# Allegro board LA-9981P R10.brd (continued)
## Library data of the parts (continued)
YG1 YL2 = Y_FSX3M-25PM20FDO_4P
YV1 = Y_7V27000011_4P

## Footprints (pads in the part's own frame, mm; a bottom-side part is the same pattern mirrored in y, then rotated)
2N7002DW-T-R7_SOT363-6
  oval 0.381x1.397 smd: 1(0,0) 2(0.65,0) 3(1.3,0) 4(1.3,1.725) 5(0.65,1.725) 6(0,1.725)
2N7002K_SOT23-3
  oval 1.016x1.524 smd: 1(0,0) 2(0.965,2.083) 3(-0.965,2.083)
2N7002KW_SOT323-3
  oval 0.813x0.914 smd: 1(0,0) 2(0.65,1.6) 3(-0.65,1.6)
2N7002W-T-R7_SOT323-3
  oval 0.813x0.914 smd: 1(0,0) 2(0.65,1.6) 3(-0.65,1.6)
74AUP1G07GW_TSSOP5
  oval 0.381x1.346 smd: 1(0,0) 2(0.65,0) 3(1.3,0) 4(1.3,1.79) 5(0,1.79)
74CBTLV3126BQ_DHVQFN14_2P5X3
  oval 1.041x0.254 smd: 1(0,0) 7(2.95,0) 8(2.95,0.5) 14(0,0.5)
  oval 0.254x1.041 smd: 2(0.475,-0.975) 3(0.975,-0.975) 4(1.475,-0.975) 5(1.975,-0.975) 6(2.475,-0.975) 9(2.475,1.475) 10(1.975,1.475) 11(1.475,1.475) 12(0.975,1.475) 13(0.475,1.475)
  rect 1.499x0.991 smd: 15(1.475,0.25)
2160809000A11SEYMOU_FCBGA_962P
  round 0.508 smd: A3(0.8,0) A37(26.8,0) A39(27.6,0) AA9(4.8,-15) AA10(5.6,-15) AA11(6.4,-14.4) AA12(7.4,-14.4) AA13(8.4,-14.4) AA15(9.4,-14.4) AA16(10.4,-14.4) AA17(11.4,-14.4) AA18(12.4,-14.4) AA20(13.4,-14.4) AA21(14.4,-14.4) AA22(15.4,-14.4) AA23(16.4,-14.4) AA24(17.4,-14.4) AA26(18.4,-14.4) AA27(19.4,-14.4) AA28(20.4,-14.4) AA29(21.2,-15) AA30(22,-15) AA31(22.8,-15) AB11(6.4,-15.4) AB12(7.4,-15.4) AB13(8.4,-15.4) AB15(9.4,-15.4) AB16(10.4,-15.4) AB17(11.4,-15.4) AB18(12.4,-15.4) AB20(13.4,-15.4) AB21(14.4,-15.4) AB22(15.4,-15.4) AB23(16.4,-15.4) AB24(17.4,-15.4) AB26(18.4,-15.4) AB27(19.4,-15.4) AB28(20.4,-15.4) AC10(5.6,-16.2) AC11(6.4,-16.4) AC12(7.4,-16.4) AC13(8.4,-16.4) AC15(9.4,-16.4) AC16(10.4,-16.4) AC17(11.4,-16.4) AC18(12.4,-16.4) AC20(13.4,-16.4) AC21(14.4,-16.4) AC22(15.4,-16.4) AC23(16.4,-16.4) AC24(17.4,-16.4) AC26(18.4,-16.4) AC27(19.4,-16.4) AC28(20.4,-16.4) AC29(21.2,-16.2) AC30(22,-16.2) AD11(6.4,-17.4) AD12(7.4,-17.4) AD13(8.4,-17.4) AD15(9.4,-17.4) AD16(10.4,-17.4) AD17(11.4,-17.4) AD18(12.4,-17.4) AD20(13.4,-17.4) AD21(14.4,-17.4) AD22(15.4,-17.4) AD23(16.4,-17.4) AD24(17.4,-17.4) AD26(18.4,-17.4) AD27(19.4,-17.4) AD28(20.4,-17.4) AD29(21.2,-17.4) AF12(7.4,-18.4) AF13(8.4,-18.4) AF15(9.4,-18.4) AF16(10.4,-18.4) AF17(11.4,-18.4) AF18(12.4,-18.4) AF20(13.4,-18.4) AF21(14.4,-18.4) AF22(15.4,-18.4) AF23(16.4,-18.4) AF24(17.4,-18.4) AF26(18.4,-18.4) AF27(19.4,-18.4) AF28(20.4,-18.4) AG13(8.4,-19.4) AG15(9.4,-19.4) AG16(10.4,-19.4) AG17(11.4,-19.4) AG18(12.4,-19.4) AG20(13.4,-19.4) AG21(14.4,-19.4) AG22(15.4,-19.4) AG23(16.4,-19.4) AG24(17.4,-19.4) AG26(18.4,-19.4) AG27(19.4,-19.4) AH15(9.4,-20.4) AH16(10.4,-20.4) AH17(11.4,-20.4) AH18(12.4,-20.4) AH20(13.4,-20.4) AH21(14.4,-20.4) AH22(15.4,-20.4) AH23(16.4,-20.4) AH24(17.4,-20.4) AH26(18.4,-20.4) AJ16(10.2,-21.2) AJ17(11.4,-21.2) AJ19(12.6,-21.2) AJ20(13.8,-21.2) AJ21(15,-21.2) AJ23(16.2,-21.2) AJ24(17.4,-21.2) AK17(11.4,-22) AK19(12.6,-22) AK20(13.8,-22) AK21(15,-22) AK23(16.2,-22) AL19(12.6,-22.8) AL20(13.8,-22.8) AL21(15,-22.8) AM20(13.8,-23.6) AU1(0,-26.8) AU3(0.8,-26.8) AU37(26.8,-26.8) AU39(27.6,-26.8) AW1(0,-27.6) AW3(0.8,-27.6) AW37(26.8,-27.6) AW39(27.6,-27.6) C1(0,-0.8) C3(0.8,-0.8) C37(26.8,-0.8) C39(27.6,-0.8) H20(13.8,-4) J19(12.6,-4.8) J20(13.8,-4.8) J21(15,-4.8) K17(11.4,-5.6) K19(12.6,-5.6) K20(13.8,-5.6) K21(15,-5.6) K23(16.2,-5.6) L16(10.4,-6.4) L17(11.4,-6.4) L18(12.4,-6.4) L20(13.4,-6.4) L21(14.4,-6.4) L22(15.4,-6.4) L23(16.4,-6.4) L24(17.4,-6.4) M15(9.4,-7.4) M16(10.4,-7.4) M17(11.4,-7.4) M18(12.4,-7.4) M20(13.4,-7.4) M21(14.4,-7.4) M22(15.4,-7.4) M23(16.4,-7.4) M24(17.4,-7.4) M26(18.4,-7.4) N13(8.4,-8.4) N15(9.4,-8.4) N16(10.4,-8.4) N17(11.4,-8.4) N18(12.4,-8.4) N20(13.4,-8.4) N21(14.4,-8.4) N22(15.4,-8.4) N23(16.4,-8.4) N24(17.4,-8.4) N26(18.4,-8.4) N27(19.4,-8.4) R12(7.4,-9.4) R13(8.4,-9.4) R15(9.4,-9.4) R16(10.4,-9.4) R17(11.4,-9.4) R18(12.4,-9.4) R20(13.4,-9.4) R21(14.4,-9.4) R22(15.4,-9.4) R23(16.4,-9.4) R24(17.4,-9.4) R26(18.4,-9.4) R27(19.4,-9.4) R28(20.4,-9.4) T11(6.4,-10.4) T12(7.4,-10.4) T13(8.4,-10.4) T15(9.4,-10.4) T16(10.4,-10.4) T17(11.4,-10.4) T18(12.4,-10.4) T20(13.4,-10.4) T21(14.4,-10.4) T22(15.4,-10.4) T23(16.4,-10.4) T24(17.4,-10.4) T26(18.4,-10.4) T27(19.4,-10.4) T28(20.4,-10.4) T29(21.2,-10.2) U10(5.6,-11.4) U11(6.4,-11.4) U12(7.4,-11.4) U13(8.4,-11.4) U15(9.4,-11.4) U16(10.4,-11.4) U17(11.4,-11.4) U18(12.4,-11.4) U20(13.4,-11.4) U21(14.4,-11.4) U22(15.4,-11.4) U23(16.4,-11.4) U24(17.4,-11.4) U26(18.4,-11.4) U27(19.4,-11.4) U28(20.4,-11.4) U29(21.2,-11.4) U30(22,-11.4) V11(6.4,-12.4) V12(7.4,-12.4) V13(8.4,-12.4) V15(9.4,-12.4) V16(10.4,-12.4) V17(11.4,-12.4) V18(12.4,-12.4) V20(13.4,-12.4) V21(14.4,-12.4) V22(15.4,-12.4) V23(16.4,-12.4) V24(17.4,-12.4) V26(18.4,-12.4) V27(19.4,-12.4) V28(20.4,-12.4) W9(4.8,-12.6) W10(5.6,-12.6) W29(21.2,-12.6) W30(22,-12.6) W31(22.8,-12.6) Y8(4,-13.8) Y9(4.8,-13.8) Y10(5.6,-13.8) Y11(6.4,-13.4) Y12(7.4,-13.4) Y13(8.4,-13.4) Y15(9.4,-13.4) Y16(10.4,-13.4) Y17(11.4,-13.4) Y18(12.4,-13.4) Y20(13.4,-13.4) Y21(14.4,-13.4) Y22(15.4,-13.4) Y23(16.4,-13.4) Y24(17.4,-13.4) Y26(18.4,-13.4) Y27(19.4,-13.4) Y28(20.4,-13.4) Y29(21.2,-13.8) Y30(22,-13.8) Y31(22.8,-13.8) Y32(23.6,-13.8)
  round 0.305 smd: A5(1.7,0) A6(2.6,0) A8(4.2,0) A10(5.8,0) A12(7.4,0) A14(9,0) A16(10.6,0) A18(12.2,0) A20(13.8,0) A22(15.4,0) A24(17,0) A26(18.6,0) A28(20.2,0) A30(21.8,0) A32(23.4,0) A34(25,0) A35(25.9,0) AA2(0.4,-14.6) AA4(1.2,-14.6) AA6(2.4,-14.8) AA34(25.2,-14.8) AA36(26.4,-14.6) AA38(27.2,-14.6) AB1(0,-15.4) AB3(0.8,-15.4) AB5(1.6,-15.4) AB6(2.4,-15.6) AB34(25.2,-15.6) AB35(26,-15.4) AB37(26.8,-15.4) AB39(27.6,-15.4) AC2(0.4,-16.2) AC4(1.2,-16.2) AC6(2.4,-16.4) AC34(25.2,-16.4) AC36(26.4,-16.2) AC38(27.2,-16.2) AD1(0,-17) AD3(0.8,-17) AD5(1.6,-17) AD6(2.4,-17.2) AD34(25.2,-17.2) AD35(26,-17) AD37(26.8,-17) AD39(27.6,-17) AE2(0.4,-17.8) AE4(1.2,-17.8) AE6(2.4,-18) AE34(25.2,-18) AE36(26.4,-17.8) AE38(27.2,-17.8) AF1(0,-18.6) AF3(0.8,-18.6) AF5(1.6,-18.6) AF6(2.4,-18.8) AF34(25.2,-18.8) AF35(26,-18.6) AF37(26.8,-18.6) AF39(27.6,-18.6) AG2(0.4,-19.4) AG4(1.2,-19.4) AG6(2.4,-19.6) AG34(25.2,-19.6) AG36(26.4,-19.4) AG38(27.2,-19.4) AH1(0,-20.2) AH3(0.8,-20.2) AH5(1.6,-20.2) AH6(2.4,-20.4) AH34(25.2,-20.4) AH35(26,-20.2) AH37(26.8,-20.2) AH39(27.6,-20.2) AJ2(0.4,-21) AJ4(1.2,-21) AJ6(2.4,-21.2) AJ34(25.2,-21.2) AJ36(26.4,-21) AJ38(27.2,-21) AK1(0,-21.8) AK3(0.8,-21.8) AK5(1.6,-21.8) AK6(2.4,-22) AK34(25.2,-22) AK35(26,-21.8) AK37(26.8,-21.8) AK39(27.6,-21.8) AL2(0.4,-22.6) AL4(1.2,-22.6) AL6(2.4,-22.8) AL34(25.2,-22.8) AL36(26.4,-22.6) AL38(27.2,-22.6) AM1(0,-23.4) AM3(0.8,-23.4) AM5(1.6,-23.4) AM6(2.4,-23.6) AM34(25.2,-23.6) AM35(26,-23.4) AM37(26.8,-23.4) AM39(27.6,-23.4) AN2(0.4,-24.2) AN4(1.2,-24.2) AN6(2.4,-24.4) AN34(25.2,-24.4) AN36(26.4,-24.2) AN38(27.2,-24.2) AP1(0,-25) AP3(0.8,-25) AP5(1.6,-25) AP6(2.4,-25.2) AP7(3.2,-25.2) AP8(4,-25.2) AP9(4.8,-25.2) AP10(5.6,-25.2) AP11(6.4,-25.2) AP12(7.2,-25.2) AP13(8,-25.2) AP14(8.8,-25.2) AP15(9.6,-25.2) AP16(10.4,-25.2) AP17(11.2,-25.2) AP18(12,-25.2) AP19(12.8,-25.2) AP20(13.8,-25.2) AP21(14.8,-25.2) AP22(15.6,-25.2) AP23(16.4,-25.2) AP24(17.2,-25.2) AP25(18,-25.2) AP26(18.8,-25.2) AP27(19.6,-25.2) AP28(20.4,-25.2) AP29(21.2,-25.2) AP30(22,-25.2) AP31(22.8,-25.2) AP32(23.6,-25.2) AP33(24.4,-25.2) AP34(25.2,-25.2) AP35(26,-25) AP37(26.8,-25) AP39(27.6,-25) AR1(0,-25.9) AR3(0.8,-25.9) AR5(1.7,-25.9) AR6(2.6,-26) AR8(4.2,-26) AR10(5.8,-26) AR12(7.4,-26) AR14(9,-26) AR16(10.6,-26) AR18(12.2,-26) AR20(13.8,-26) AR22(15.4,-26) AR24(17,-26) AR26(18.6,-26) AR28(20.2,-26) AR30(21.8,-26) AR32(23.4,-26) AR34(25,-26) AR35(25.9,-25.9) AR37(26.8,-25.9) AR39(27.6,-25.9) AT7(3.4,-26.4) AT9(5,-26.4) AT11(6.6,-26.4) AT13(8.2,-26.4) AT15(9.8,-26.4) AT17(11.4,-26.4) AT19(13,-26.4) AT21(14.6,-26.4) AT23(16.2,-26.4) AT25(17.8,-26.4) AT27(19.4,-26.4) AT29(21,-26.4) AT31(22.6,-26.4) AT33(24.2,-26.4) AU5(1.7,-26.8) AU6(2.6,-26.8) AU8(4.2,-26.8) AU10(5.8,-26.8) AU12(7.4,-26.8) AU14(9,-26.8) AU16(10.6,-26.8) AU18(12.2,-26.8) AU20(13.8,-26.8) AU22(15.4,-26.8) AU24(17,-26.8) AU26(18.6,-26.8) AU28(20.2,-26.8) AU30(21.8,-26.8) AU32(23.4,-26.8) AU34(25,-26.8) AU35(25.9,-26.8) AV7(3.4,-27.2) AV9(5,-27.2) AV11(6.6,-27.2) AV13(8.2,-27.2) AV15(9.8,-27.2) AV17(11.4,-27.2) AV19(13,-27.2) AV21(14.6,-27.2) AV23(16.2,-27.2) AV25(17.8,-27.2) AV27(19.4,-27.2) AV29(21,-27.2) AV31(22.6,-27.2) AV33(24.2,-27.2) AW5(1.7,-27.6) AW6(2.6,-27.6) AW8(4.2,-27.6) AW10(5.8,-27.6) AW12(7.4,-27.6) AW14(9,-27.6) AW16(10.6,-27.6) AW18(12.2,-27.6) AW20(13.8,-27.6) AW22(15.4,-27.6) AW24(17,-27.6) AW26(18.6,-27.6) AW28(20.2,-27.6) AW30(21.8,-27.6) AW32(23.4,-27.6) AW34(25,-27.6) AW35(25.9,-27.6) B7(3.4,-0.4) B9(5,-0.4) B11(6.6,-0.4) B13(8.2,-0.4) B15(9.8,-0.4) B17(11.4,-0.4) B19(13,-0.4) B21(14.6,-0.4) B23(16.2,-0.4) B25(17.8,-0.4) B27(19.4,-0.4) B29(21,-0.4) B31(22.6,-0.4) B33(24.2,-0.4) C5(1.7,-0.8) C6(2.6,-0.8) C8(4.2,-0.8) C10(5.8,-0.8) C12(7.4,-0.8) C14(9,-0.8) C16(10.6,-0.8) C18(12.2,-0.8) C20(13.8,-0.8) C22(15.4,-0.8) C24(17,-0.8) C26(18.6,-0.8) C28(20.2,-0.8) C30(21.8,-0.8) C32(23.4,-0.8) C34(25,-0.8) C35(25.9,-0.8) D7(3.4,-1.2) D9(5,-1.2) D11(6.6,-1.2) D13(8.2,-1.2) D15(9.8,-1.2) D17(11.4,-1.2) D19(13,-1.2) D21(14.6,-1.2) D23(16.2,-1.2) D25(17.8,-1.2) D27(19.4,-1.2) D29(21,-1.2) D31(22.6,-1.2) D33(24.2,-1.2) E1(0,-1.7) E3(0.8,-1.7) E5(1.7,-1.7) E6(2.6,-1.6) E8(4.2,-1.6) E10(5.8,-1.6) E12(7.4,-1.6) E14(9,-1.6) E16(10.6,-1.6) E18(12.2,-1.6) E20(13.8,-1.6) E22(15.4,-1.6) E24(17,-1.6) E26(18.6,-1.6) E28(20.2,-1.6) E30(21.8,-1.6) E32(23.4,-1.6) E34(25,-1.6) E35(25.9,-1.7) E37(26.8,-1.7) E39(27.6,-1.7) F1(0,-2.6) F3(0.8,-2.6) F5(1.6,-2.6) F6(2.4,-2.4) F7(3.2,-2.4) F8(4,-2.4) F9(4.8,-2.4) F10(5.6,-2.4) F11(6.4,-2.4) F12(7.2,-2.4) F13(8,-2.4) F14(8.8,-2.4) F15(9.6,-2.4) F16(10.4,-2.4) F17(11.2,-2.4) F18(12,-2.4) F19(12.8,-2.4) F20(13.8,-2.4) F21(14.8,-2.4) F22(15.6,-2.4) F23(16.4,-2.4) F24(17.2,-2.4) F25(18,-2.4) F26(18.8,-2.4) F27(19.6,-2.4) F28(20.4,-2.4) F29(21.2,-2.4) F30(22,-2.4) F31(22.8,-2.4) F32(23.6,-2.4) F33(24.4,-2.4) F34(25.2,-2.4) F35(26,-2.6) F37(26.8,-2.6) F39(27.6,-2.6) G2(0.4,-3.4) G4(1.2,-3.4) G6(2.4,-3.2) G34(25.2,-3.2) G36(26.4,-3.4) G38(27.2,-3.4) H1(0,-4.2) H3(0.8,-4.2) H5(1.6,-4.2) H6(2.4,-4) H34(25.2,-4) H35(26,-4.2) H37(26.8,-4.2) H39(27.6,-4.2) J2(0.4,-5) J4(1.2,-5) J6(2.4,-4.8) J34(25.2,-4.8) J36(26.4,-5) J38(27.2,-5) K1(0,-5.8) K3(0.8,-5.8) K5(1.6,-5.8) K6(2.4,-5.6) K34(25.2,-5.6) K35(26,-5.8) K37(26.8,-5.8) K39(27.6,-5.8) L2(0.4,-6.6) L4(1.2,-6.6) L6(2.4,-6.4) L34(25.2,-6.4) L36(26.4,-6.6) L38(27.2,-6.6) M1(0,-7.4) M3(0.8,-7.4) M5(1.6,-7.4) M6(2.4,-7.2) M34(25.2,-7.2) M35(26,-7.4) M37(26.8,-7.4) M39(27.6,-7.4) N2(0.4,-8.2) N4(1.2,-8.2) N6(2.4,-8) N34(25.2,-8) N36(26.4,-8.2) N38(27.2,-8.2) P1(0,-9) P3(0.8,-9) P5(1.6,-9) P6(2.4,-8.8) P34(25.2,-8.8) P35(26,-9) P37(26.8,-9) P39(27.6,-9) R2(0.4,-9.8) R4(1.2,-9.8) R6(2.4,-9.6) R34(25.2,-9.6) R36(26.4,-9.8) R38(27.2,-9.8) T1(0,-10.6) T3(0.8,-10.6) T5(1.6,-10.6) T6(2.4,-10.4) T34(25.2,-10.4) T35(26,-10.6) T37(26.8,-10.6) T39(27.6,-10.6) U2(0.4,-11.4) U4(1.2,-11.4) U6(2.4,-11.2) U34(25.2,-11.2) U36(26.4,-11.4) U38(27.2,-11.4) V1(0,-12.2) V3(0.8,-12.2) V5(1.6,-12.2) V6(2.4,-12) V34(25.2,-12) V35(26,-12.2) V37(26.8,-12.2) V39(27.6,-12.2) W2(0.4,-13) W4(1.2,-13) W6(2.4,-12.8) W34(25.2,-12.8) W36(26.4,-13) W38(27.2,-13) Y1(0,-13.8) Y3(0.8,-13.8) Y5(1.6,-13.8) Y6(2.4,-13.8) Y34(25.2,-13.8) Y35(26,-13.8) Y37(26.8,-13.8) Y39(27.6,-13.8)
  round 0.406 smd: AA7(3.2,-15) AA8(4,-15) AA32(23.6,-15) AA33(24.4,-15) AC7(3.2,-16.2) AC8(4,-16.2) AC9(4.8,-16.2) AC31(22.8,-16.2) AC32(23.6,-16.2) AC33(24.4,-16.2) AD7(3.2,-17.4) AD8(4,-17.4) AD9(4.8,-17.4) AD10(5.6,-17.4) AD30(22,-17.4) AD31(22.8,-17.4) AD32(23.6,-17.4) AD33(24.4,-17.4) AF7(3.2,-18.6) AF8(4,-18.6) AF9(4.8,-18.6) AF10(5.6,-18.6) AF11(6.4,-18.4) AF29(21.2,-18.6) AF30(22,-18.6) AF31(22.8,-18.6) AF32(23.6,-18.6) AF33(24.4,-18.6) AG7(3.2,-19.8) AG8(4,-19.8) AG9(4.8,-19.8) AG10(5.6,-19.8) AG11(6.4,-19.4) AG12(7.4,-19.4) AG28(20.4,-19.4) AG29(21.2,-19.8) AG30(22,-19.8) AG31(22.8,-19.8) AG32(23.6,-19.8) AG33(24.4,-19.8) AH11(6.4,-20.4) AH12(7.4,-20.4) AH13(8.4,-20.4) AH27(19.4,-20.4) AH28(20.4,-20.4) AH29(21.2,-20.6) AJ7(3.2,-21) AJ8(4,-21) AJ9(4.8,-21) AJ10(5.6,-21) AJ11(6.6,-21.2) AJ13(7.8,-21.2) AJ14(9,-21.2) AJ26(18.6,-21.2) AJ27(19.8,-21.2) AJ28(20.6,-21.2) AJ30(22,-21) AJ31(22.8,-21) AJ32(23.6,-21) AJ33(24.4,-21) AK7(3.2,-22) AK8(4,-22) AK9(4.8,-22) AK10(5.6,-22) AK11(6.6,-22) AK13(7.8,-22) AK14(9,-22) AK16(10.2,-22) AK24(17.4,-22) AK26(18.6,-22) AK27(19.8,-22) AK29(21,-22) AK30(22,-22) AK31(22.8,-22) AK32(23.6,-22) AK33(24.4,-22) AL7(3.2,-22.8) AL8(4,-22.8) AL9(4.8,-22.8) AL10(5.6,-22.8) AL11(6.6,-22.8) AL13(7.8,-22.8) AL14(9,-22.8) AL16(10.2,-22.8) AL17(11.4,-22.8) AL23(16.2,-22.8) AL24(17.4,-22.8) AL26(18.6,-22.8) AL27(19.8,-22.8) AL29(21,-22.8) AL30(22,-22.8) AL31(22.8,-22.8) AL32(23.6,-22.8) AL33(24.4,-22.8) AM7(3.2,-23.6) AM8(4,-23.6) AM9(4.8,-23.6) AM10(5.6,-23.6) AM11(6.6,-23.6) AM13(7.8,-23.6) AM14(9,-23.6) AM16(10.2,-23.6) AM17(11.4,-23.6) AM19(12.6,-23.6) AM21(15,-23.6) AM23(16.2,-23.6) AM24(17.4,-23.6) AM26(18.6,-23.6) AM27(19.8,-23.6) AM29(21,-23.6) AM30(22,-23.6) AM31(22.8,-23.6) AM32(23.6,-23.6) AM33(24.4,-23.6) AN7(3.2,-24.4) AN8(4,-24.4) AN9(4.8,-24.4) AN10(5.6,-24.4) AN11(6.6,-24.4) AN13(7.8,-24.4) AN14(9,-24.4) AN16(10.2,-24.4) AN17(11.4,-24.4) AN19(12.6,-24.4) AN20(13.8,-24.4) AN21(15,-24.4) AN23(16.2,-24.4) AN24(17.4,-24.4) AN26(18.6,-24.4) AN27(19.8,-24.4) AN29(21,-24.4) AN30(22,-24.4) AN31(22.8,-24.4) AN32(23.6,-24.4) AN33(24.4,-24.4) G7(3.2,-3.2) G8(4,-3.2) G9(4.8,-3.2) G10(5.6,-3.2) G11(6.6,-3.2) G13(7.8,-3.2) G14(9,-3.2) G16(10.2,-3.2) G17(11.4,-3.2) G19(12.6,-3.2) G20(13.8,-3.2) G21(15,-3.2) G23(16.2,-3.2) G24(17.4,-3.2) G26(18.6,-3.2) G27(19.8,-3.2) G29(21,-3.2) G30(22,-3.2) G31(22.8,-3.2) G32(23.6,-3.2) G33(24.4,-3.2) H7(3.2,-4) H8(4,-4) H9(4.8,-4) H10(5.6,-4) H11(6.6,-4) H13(7.8,-4) H14(9,-4) H16(10.2,-4) H17(11.4,-4) H19(12.6,-4) H21(15,-4) H23(16.2,-4) H24(17.4,-4) H26(18.6,-4) H27(19.8,-4) H29(21,-4) H30(22,-4) H31(22.8,-4) H32(23.6,-4) H33(24.4,-4) J7(3.2,-4.8) J8(4,-4.8) J9(4.8,-4.8) J10(5.6,-4.8) J11(6.6,-4.8) J13(7.8,-4.8) J14(9,-4.8) J16(10.2,-4.8) J17(11.4,-4.8) J23(16.2,-4.8) J24(17.4,-4.8) J26(18.6,-4.8) J27(19.8,-4.8) J29(21,-4.8) J30(22,-4.8) J31(22.8,-4.8) J32(23.6,-4.8) J33(24.4,-4.8) K7(3.2,-5.6) K8(4,-5.6) K9(4.8,-5.6) K10(5.6,-5.6) K11(6.6,-5.6) K13(7.8,-5.6) K14(9,-5.6) K16(10.2,-5.6) K24(17.4,-5.6) K26(18.6,-5.6) K27(19.8,-5.6) K29(21,-5.6) K30(22,-5.6) K31(22.8,-5.6) K32(23.6,-5.6) K33(24.4,-5.6) L7(3.2,-6.6) L8(4,-6.6) L9(4.8,-6.6) L10(5.6,-6.6) L11(6.4,-6.4) L12(7.4,-6.4) L13(8.4,-6.4) L15(9.4,-6.4) L26(18.4,-6.4) L27(19.4,-6.4) L28(20.4,-6.4) L29(21.2,-6.6) L30(22,-6.6) L31(22.8,-6.6) L32(23.6,-6.6) L33(24.4,-6.6) M11(6.4,-7.4) M12(7.4,-7.4) M13(8.4,-7.4) M27(19.4,-7.4) M28(20.4,-7.4) N7(3.2,-7.8) N8(4,-7.8) N9(4.8,-7.8) N10(5.6,-7.8) N11(6.4,-8.4) N12(7.4,-8.4) N28(20.4,-8.4) N29(21.2,-7.8) N30(22,-7.8) N31(22.8,-7.8) N32(23.6,-7.8) N33(24.4,-7.8) P7(3.2,-9) P8(4,-9) P9(4.8,-9) P10(5.6,-9) P29(21.2,-9) P30(22,-9) P31(22.8,-9) P32(23.6,-9) P33(24.4,-9) R11(6.4,-9.4) T7(3.2,-10.2) T8(4,-10.2) T9(4.8,-10.2) T10(5.6,-10.2) T30(22,-10.2) T31(22.8,-10.2) T32(23.6,-10.2) T33(24.4,-10.2) U7(3.2,-11.4) U8(4,-11.4) U9(4.8,-11.4) U31(22.8,-11.4) U32(23.6,-11.4) U33(24.4,-11.4) W7(3.2,-12.6) W8(4,-12.6) W32(23.6,-12.6) W33(24.4,-12.6) Y7(3.2,-13.8) Y33(24.4,-13.8)
ACES_50299-00501-003_5P
  round 1.803 hole 1.803 unplated: (-0.2,5.2) (8.2,5.2)
  oval 0.889x2.388 smd: 1(0,0) 2(2,0) 3(4,0) 4(6,0) 5(8,0)
ACES_85204-0300N_3P
  oval 0.787x1.6 smd: 1(0,0) 2(1.25,0) 3(2.5,0)
  rect 2.108x2.997 smd: 4(-2.55,-2.9) 5(5.05,-2.9)
ACES_88460-00601-P01_6P
  oval 0.508x0.991 smd: 1(0,0) 2(0.8,0) 3(1.6,0) 4(2.4,0) 5(3.2,0) 6(4,0)
  rect 1.194x1.702 smd: 7(-1.3,-1.95) 8(5.3,-1.95)
ACON_TARA4-9K1311_9P
  round 1.194 hole 0.711: 1(0,0) 2(-2.5,0) 3(-4.5,0) 4(-7,0) 5(-7.5,-1.5) 6(-5.5,-1.5) 7(-3.5,-1.5) 8(-1.5,-1.5) 9(0.5,-1.5)
  oval 1.397x2.591 hole 0.787x2.007: 10(-11.35,-1.59) 13(4.35,-1.59)
  oval 1.397x2.388 hole 0.787x1.803: 11(-11.35,-9.09) 12(4.35,-9.09)
ACON_UARBG-4K1926_4P
  round 1.422 hole 0.914: 1(0,0) 2(-2.5,0) 3(-4.5,0) 4(-7,0)
  oval 1.397x2.819 hole 0.889x2.311: 5(-9.9,0) 6(2.9,0)
  oval 1.219x2.108 hole 0.711x1.6: 7(-11.2,-7.45) 8(4.2,-7.45)
ALC3221-CG_MQFN48_6X6
  oval 0.203x1.041 smd: 1(0,0) 2(0.4,0) 3(0.8,0) 4(1.2,0) 5(1.6,0) 6(2,0) 7(2.4,0) 8(2.8,0) 9(3.2,0) 10(3.6,0) 11(4,0) 12(4.4,0) 25(4.4,5.95) 26(4,5.95) 27(3.6,5.95) 28(3.2,5.95) 29(2.8,5.95) 30(2.4,5.95) 31(2,5.95) 32(1.6,5.95) 33(1.2,5.95) 34(0.8,5.95) 35(0.4,5.95) 36(0,5.95)
  oval 1.041x0.203 smd: 13(5.175,0.775) 14(5.175,1.175) 15(5.175,1.575) 16(5.175,1.975) 17(5.175,2.375) 18(5.175,2.775) 19(5.175,3.175) 20(5.175,3.575) 21(5.175,3.975) 22(5.175,4.375) 23(5.175,4.775) 24(5.175,5.175) 37(-0.775,5.175) 38(-0.775,4.775) 39(-0.775,4.375) 40(-0.775,3.975) 41(-0.775,3.575) 42(-0.775,3.175) 43(-0.775,2.775) 44(-0.775,2.375) 45(-0.775,1.975) 46(-0.775,1.575) 47(-0.775,1.175) 48(-0.775,0.775)
  rect 4.394x4.394 smd: 49(2.2,2.975)
AO4407AL_SO8
  oval 0.635x1.854 smd: 1(0,0) 2(1.27,0) 3(2.54,0) 4(3.81,0) 5(3.81,5.165) 6(2.54,5.165) 7(1.27,5.165) 8(0,5.165)
AP2301GN-HF_SOT23-3
  oval 1.016x1.524 smd: 1(0,0) 2(0.965,2.083) 3(-0.965,2.083)
AP2301MPG-13_MSOP8
  oval 0.381x1.626 smd: 1(0,0) 2(0.65,0) 3(1.3,0) 4(1.95,0) 5(1.95,4.3) 6(1.3,4.3) 7(0.65,4.3) 8(0,4.3)
  rect 1.803x1.499 smd: 9(0.975,2.15)
APL3512ABI-TRG_SOT23-5
  oval 0.61x1.041 smd: 1(0,0) 2(0.95,0) 3(1.9,0) 4(1.9,2.7) 5(0,2.7)
AZ5125-02SPR7G_SOT23-3
  oval 1.016x1.524 smd: 1(0,0) 2(0.965,2.083) 3(-0.965,2.083)
BAT54C-7-F_SOT23-3
  oval 1.016x1.524 smd: 1(0,0) 2(0.965,2.083) 3(-0.965,2.083)
BAT54CW_SOT323-3
  oval 0.66x0.864 smd: 1(0,0) 2(-0.65,-1.85) 3(0.65,-1.85)
BOTH_NS0013LF_16P
  oval 0.762x1.905 smd: 1(0,0) 2(1.27,0) 3(2.54,0) 4(3.81,0) 5(5.08,0) 6(6.35,0) 7(7.62,0) 8(8.89,0) 9(8.89,8.8) 10(7.62,8.8) 11(6.35,8.8) 12(5.08,8.8) 13(3.81,8.8) 14(2.54,8.8) 15(1.27,8.8) 16(0,8.8)
BQ24738RGRR_QFN20_3P5X3P5
  oval 0.254x1.041 smd: 1(0,0) 2(0.5,0) 3(1,0) 4(1.5,0) 5(2,0) 11(2,3.45) 12(1.5,3.45) 13(1,3.45) 14(0.5,3.45) 15(0,3.45)
  oval 1.041x0.254 smd: 6(2.725,0.725) 7(2.725,1.225) 8(2.725,1.725) 9(2.725,2.225) 10(2.725,2.725) 16(-0.725,2.725) 17(-0.725,2.225) 18(-0.725,1.725) 19(-0.725,1.225) 20(-0.725,0.725)
  rect 2.057x2.057 smd: 21(1,1.725)
BSS138-G_SOT23-3
  oval 1.016x1.524 smd: 1(0,0) 2(0.965,2.083) 3(-0.965,2.083)
C_0402
  rect 0.508x0.559 smd: 1(0,0) 2(0.914,0)
C_0603
  rect 0.635x0.889 smd: 1(0,0) 2(1.397,0)
C_0805
  rect 0.813x1.397 smd: 1(0,0) 2(1.702,0)
C_1206
  rect 1.016x1.651 smd: 1(0,0) 2(2.667,0)
C_B2
  rect 1.346x2.692 smd: 1(0,0) 2(-2.75,0)
C_D1
  rect 1.803x2.794 smd: 1(0,0) 2(6.5,0)
C_D2
  rect 2.388x2.794 smd: 1(0,0) 2(6.4,0)
C_D3
  rect 2.388x2.794 smd: 1(0,0) 2(6.4,0)
C_EEEFZ1E101P
  oval 3.2x1.6 smd: 1(0,0) 2(5,0)
C_MP6VLPS220MC4R2
  oval 3.505x1.6 smd: 1(0,0) 2(-5.6,0)
C_MP6VU330MC6
  oval 3.505x1.6 smd: 1(0,0) 2(5.6,0)
CHENG_MBK1608121YZF_2P
  rect 0.991x0.787 smd: 1(0,0) 2(1.6,0)
CHENG_SMB3025500YA_2P
  rect 2.997x1.803 smd: 1(0,0) 2(4,0)
CHT_C8BBPH853025_2P
  rect 2.54x1.397 smd: 1(-3.81,0) 2(3.81,0)
CONCR_525B01BE17A_52P
  round 1.6 hole 1.6 unplated: (-5.075,-4.85) (28.675,-4.85)
  oval 0.61x1.473 hole 0.406x0.711: 1(0,0) 3(0.8,0) 5(1.6,0) 7(2.4,0) 9(3.2,0) 11(4,0) 13(4.8,0) 15(5.6,0) 17(9.6,0) 19(10.4,0) 21(11.2,0) 23(12,0) 25(12.8,0) 27(13.6,0) 29(14.4,0) 31(15.2,0) 33(16,0) 35(16.8,0) 37(17.6,0) 39(18.4,0) 41(19.2,0) 43(20,0) 45(20.8,0) 47(21.6,0) 49(22.4,0) 51(23.2,0)
  oval 0.61x2.007 smd: 2(0.4,2.5) 4(1.2,2.5) 6(2,2.5) 8(2.8,2.5) 10(3.6,2.5) 12(4.4,2.5) 14(5.2,2.5) 16(6,2.5) 18(10,2.5) 20(10.8,2.5) 22(11.6,2.5) 24(12.4,2.5) 26(13.2,2.5) 28(14,2.5) 30(14.8,2.5) 32(15.6,2.5) 34(16.4,2.5) 36(17.2,2.5) 38(18,2.5) 40(18.8,2.5) 42(19.6,2.5) 44(20.4,2.5) 46(21.2,2.5) 48(22,2.5) 50(22.8,2.5) 52(23.6,2.5)
  oval 1.549x2.769 hole 0.787x2.007: 53(28.675,-7.65) 54(-5.075,-7.65)
CSD87312Q3E_SON8-4
  rect 2.388x0.66 smd: 1(0,0)
  rect 0.432x0.66 smd: 2(0.975,2.95)
  rect 1.753x0.66 smd: 3(-0.325,2.95)
  custom 0.475x0.475 smd: 4(0,1.475)
CSD97374CQ4M_SON8_3P5X4P5-S
  oval 0.203x0.914 smd: 1(0,0) 2(0.4,0) 3(0.8,0) 6(0.8,3.505) 7(0.4,3.505) 8(0,3.505)
  custom 0.225x0.225 smd: 4(2.2,0.265) 5(2.2,3.24)
  rect 4.039x2.21 smd: 9(1.6,1.752)
CYNTE_PCMB053T-1R0MS_2P
  rect 1.905x2.794 smd: 1(0,0) 2(4.1,0)
CYNTE_PCMB063T-1R0MS_2P
  rect 2.159x3.505 smd: 1(0,0) 2(5.85,0)
CYNTE_PG031B-4R7MS_2P
  rect 0.889x1.194 smd: 1(0,0) 2(2.2,0)
DMN66D0LDW-7_SOT363-6
  oval 0.432x0.61 smd: 1(0,0) 2(0.65,0) 3(1.3,0) 4(1.3,1.9) 5(0.65,1.9) 6(0,1.9)
E-T_3703-Q04N-11R_4P
  oval 0.61x1.549 smd: 1(0,0) 2(1,0) 3(2,0) 4(3,0)
  rect 1.194x2.007 smd: 5(4.3,-3.775) 6(-1.3,-3.775)
F_1206L150PR
  rect 0.991x1.803 smd: 1(0,0) 2(2.8,0)
FDV301N_NL_SOT23-3
  oval 1.016x1.524 smd: 1(0,0) 2(0.965,2.083) 3(-0.965,2.083)
FIDUCIAL_C40M80
  round 1.016 smd: 1(0,0)
G993P1UF_SOP8
  oval 0.635x1.854 smd: 1(0,0) 2(1.27,0) 3(2.54,0) 4(3.81,0) 5(3.81,5.165) 6(2.54,5.165) 7(1.27,5.165) 8(0,5.165)
H_2P8
  round 3.302 hole 2.794: 1(0,0)
H_3P3
  round 3.81 hole 3.302: 1(0,0)
H_3P7
  round 4.216 hole 3.708: 1(0,0)
H_3P7X3P2N
  oval 3.708x3.2 hole 3.708x3.2 unplated: (0,0)
HASWELL-MCP-E-ULT_BGA_1168P-T
  round 0.508 smd: A3(-1.137,0) A62(-38.036,0) AW1(0,22.042) AW63(-38.628,22.057) AY2(-0.543,22.628) AY62(-38.062,22.628) B2(-0.508,0.508) B63(-38.628,0.592) C1(0,1.137)
  round 0.381 smd: A4(-1.894,0) A5(-2.554,0) A6(-3.75,0) A59(-35.9,0) A60(-36.726,0) A61(-37.386,0) AA9(-5.032,11.576) AA21(-11.688,11.489) AA23(-13.115,11.489) AA58(-35.377,11.33) AB10(-5.476,12.053) AB20(-11.18,11.896) AB21(-11.688,12.302) AB22(-12.607,11.896) AB23(-13.115,12.302) AB57(-35.057,11.98) AC9(-5.032,12.529) AC20(-11.18,12.709) AC22(-12.607,12.709) AC58(-35.377,12.63) AD10(-5.476,13.005) AD21(-11.688,13.115) AD23(-13.115,13.115) AD57(-35.057,13.28) AE9(-5.032,13.481) AE10(-5.476,13.958) AE20(-11.18,13.521) AE21(-11.688,13.928) AE22(-12.607,13.521) AE23(-13.115,13.928) AE58(-35.377,13.931) AF9(-5.032,14.434) AF11(-6.059,14.282) AF12(-6.872,14.282) AF14(-7.685,14.282) AF15(-8.497,14.282) AF17(-9.31,14.282) AF18(-10.123,14.282) AF20(-10.936,14.282) AF22(-12.607,14.334) AG10(-5.653,14.79) AG11(-6.465,14.79) AG13(-7.278,14.79) AG14(-8.091,14.79) AG16(-8.904,14.79) AG17(-9.717,14.79) AG19(-10.529,14.79) AG20(-11.342,14.79) AG23(-13.115,14.741) AG57(-35.057,14.581) AG58(-35.692,15.009) AH22(-12.607,15.147) AH24(-13.92,15.289) AH26(-15.22,15.289) AH28(-16.521,15.289) AH30(-17.821,15.289) AH32(-19.122,15.289) AH34(-20.422,15.289) AH36(-21.723,15.289) AH38(-23.023,15.289) AH40(-24.324,15.289) AH42(-25.624,15.289) AH44(-26.925,15.289) AH46(-28.225,15.289) AH49(-29.526,15.289) AH51(-30.826,15.289) AH53(-32.127,15.289) AH55(-33.427,15.289) AH57(-34.728,15.289) AJ23(-13.115,15.553) AJ25(-14.57,15.614) AJ27(-15.871,15.614) AJ29(-17.171,15.614) AJ31(-18.472,15.614) AJ33(-19.772,15.614) AJ35(-21.073,15.614) AJ37(-22.373,15.614) AJ39(-23.674,15.614) AJ41(-24.974,15.614) AJ43(-26.275,15.614) AJ45(-27.575,15.614) AJ47(-28.875,15.614) AJ50(-30.176,15.614) AJ52(-31.476,15.614) AJ54(-32.777,15.614) AJ56(-34.077,15.614) AJ58(-35.378,15.614) AT1(0,19.997) AT63(-38.628,19.848) AU1(0,20.657) AU63(-38.628,20.673) AV1(0,21.318) AV2(-0.66,21.308) AV62(-37.978,21.318) AV63(-38.628,21.333) AW2(-0.66,21.968) AW3(-1.321,21.968) AW61(-37.328,21.978) AW62(-37.978,21.978) AY3(-1.267,22.628) AY4(-1.928,22.628) AY5(-2.588,22.628) AY59(-36.088,22.628) AY60(-36.748,22.628) AY61(-37.409,22.628) B3(-1.259,0.65) B61(-37.315,0.66) B62(-37.978,0.724) C2(-0.65,1.259) C62(-37.978,1.384) C63(-38.628,1.316) D1(0,1.861) D63(-38.628,1.976) E1(0,2.522) E23(-13.333,2.601) E25(-14.714,2.601) E27(-15.84,2.601) E29(-17.221,2.601) E31(-18.348,2.601) E33(-19.729,2.601) E35(-20.855,2.601) E37(-22.236,2.601) E39(-23.363,2.601) E41(-24.744,2.601) E43(-25.87,2.601) E45(-27.251,2.601) E47(-28.378,2.601) E49(-29.759,2.601) E51(-30.885,2.601) E53(-32.266,2.601) E55(-33.393,2.601) E57(-34.774,2.601) E63(-38.628,2.647) F1(0,3.436) F22(-12.717,3.058) F24(-14.023,3.126) F26(-15.277,3.126) F28(-16.531,3.126) F30(-17.785,3.126) F32(-19.038,3.126) F34(-20.292,3.126) F36(-21.546,3.126) F38(-22.8,3.126) F40(-24.053,3.126) F42(-25.307,3.126) F44(-26.561,3.126) F46(-27.815,3.126) F48(-29.068,3.126) F50(-30.322,3.126) F52(-31.576,3.126) F54(-32.83,3.126) F56(-34.083,3.126) F58(-35.377,3.126) G22(-12.607,3.768) G23(-13.333,3.451) G25(-14.714,3.451) G27(-15.84,3.451) G29(-17.221,3.451) G31(-18.348,3.451) G33(-19.729,3.451) G35(-20.855,3.451) G37(-22.236,3.451) G39(-23.363,3.451) G41(-24.744,3.451) G43(-25.87,3.451) G45(-27.251,3.451) G47(-28.378,3.451) G49(-29.759,3.451) G51(-30.885,3.451) G53(-32.266,3.451) G55(-33.393,3.451) G57(-34.774,3.451) H22(-12.607,4.581) H23(-13.115,4.174) H57(-35.057,4.101) J22(-12.607,5.393) J23(-13.115,4.987) J58(-35.377,4.827) K9(-5.032,5.861) K10(-5.935,5.7) K12(-6.888,5.7) K14(-7.84,5.7) K16(-8.793,5.7) K18(-9.745,5.7) K19(-10.698,5.7) K21(-11.65,5.7) K23(-13.115,5.8) K57(-35.057,5.478) L10(-5.476,6.338) L11(-6.412,6.144) L13(-7.364,6.144) L15(-8.317,6.144) L17(-9.269,6.144) L18(-10.222,6.144) L20(-11.18,6.206) L22(-12.607,6.206) L58(-35.377,6.128) M9(-5.032,6.814) M20(-11.18,7.019) M21(-11.688,6.613) M22(-12.607,7.019) M23(-13.115,6.613) M57(-35.057,6.778) N10(-5.476,7.29) N21(-11.688,7.425) N23(-13.115,7.425) N58(-35.377,7.428) P9(-5.032,7.766) P20(-11.18,7.832) P22(-12.607,7.832) P57(-35.057,8.078) R10(-5.476,8.243) R20(-11.18,8.645) R21(-11.688,8.238) R22(-12.607,8.645) R23(-13.115,8.238) T9(-5.032,8.719) T21(-11.688,9.051) T23(-13.115,9.051) T58(-35.377,8.729) U9(-5.032,9.671) U10(-5.476,9.195) U20(-11.18,9.457) U22(-12.607,9.457) U57(-35.057,9.379) V10(-5.476,10.148) V21(-11.688,9.864) V23(-13.115,9.864) V58(-35.377,10.029) W9(-5.032,10.624) W20(-11.18,10.27) W21(-11.688,10.677) W22(-12.607,10.27) W23(-13.115,10.677) W57(-35.057,10.679) Y10(-5.476,11.1) Y20(-11.18,11.083) Y22(-12.607,11.083)
  round 0.305 smd: A8(-4.538,0) A9(-5.452,0) A11(-6.367,0) A12(-7.116,0) A14(-8.03,0) A15(-8.945,0) A17(-9.694,0) A18(-10.608,0) A20(-11.523,0) A21(-12.272,0) A23(-13.186,0) A24(-14.023,0.325) A25(-14.714,0) A27(-15.84,0) A28(-16.531,0.325) A29(-17.221,0) A31(-18.348,0) A32(-19.038,0.325) A33(-19.729,0) A35(-20.855,0) A36(-21.546,0.325) A37(-22.236,0) A39(-23.363,0) A40(-24.053,0.325) A41(-24.744,0) A43(-25.87,0) A44(-26.561,0.325) A45(-27.251,0) A47(-28.378,0) A48(-29.068,0.325) A49(-29.759,0) A51(-30.885,0) A52(-31.576,0.325) A53(-32.266,0) A55(-33.393,0) A56(-34.083,0.325) A57(-34.774,0) AA1(0,11.717) AA2(-0.65,11.717) AA3(-1.3,11.678) AA4(-1.951,11.678) AA59(-36.027,11.638) AA60(-36.678,11.638) AA61(-37.328,11.638) AA62(-37.978,11.676) AA63(-38.628,11.676) AB5(-2.637,12.053) AB6(-3.287,12.053) AB7(-3.937,12.053) AB8(-4.587,12.053) AC1(0,12.466) AC2(-0.65,12.466) AC3(-1.3,12.504) AC4(-1.951,12.504) AC59(-36.027,12.464) AC60(-36.678,12.464) AC61(-37.328,12.464) AC62(-37.978,12.426) AC63(-38.628,12.426) AD1(0,13.215) AD2(-0.65,13.215) AD3(-1.3,13.177) AD4(-1.951,13.177) AD5(-2.637,13.005) AD6(-3.287,13.005) AD7(-3.937,13.005) AD8(-4.587,13.005) AD59(-36.027,13.137) AD60(-36.678,13.137) AD61(-37.328,13.137) AD62(-37.978,13.175) AD63(-38.628,13.175) AE5(-2.637,13.958) AE6(-3.287,13.958) AE7(-3.937,13.958) AE8(-4.587,13.958) AE59(-36.027,13.962) AE60(-36.678,13.962) AE61(-37.328,13.962) AE62(-37.978,13.924) AE63(-38.628,13.924) AF1(0,13.964) AF2(-0.65,13.964) AF3(-1.3,14.003) AF4(-1.951,14.003) AG1(0,14.714) AG2(-0.65,14.714) AG3(-1.3,14.676) AG4(-1.951,14.676) AG5(-2.637,14.91) AG6(-3.287,14.91) AG7(-3.937,14.91) AG8(-4.587,14.91) AG21(-11.955,15.122) AG60(-36.352,14.602) AG61(-37.003,14.602) AG62(-37.653,14.602) AG63(-38.303,14.602) AH1(0,15.463) AH2(-0.65,15.463) AH3(-1.3,15.501) AH4(-1.951,15.501) AH10(-5.653,15.476) AH11(-6.465,15.476) AH13(-7.278,15.476) AH14(-8.091,15.476) AH16(-8.904,15.476) AH17(-9.717,15.476) AH19(-10.529,15.476) AH20(-11.342,15.476) AH60(-36.678,15.278) AH61(-37.328,15.278) AH62(-37.978,15.278) AH63(-38.628,15.278) AJ5(-2.637,15.863) AJ6(-3.287,15.863) AJ7(-3.937,15.863) AJ8(-4.587,15.863) AJ10(-5.653,16.126) AJ11(-6.465,16.126) AJ13(-7.278,16.126) AJ14(-8.091,16.126) AJ60(-36.352,15.954) AJ61(-37.003,15.954) AJ62(-37.653,15.954) AJ63(-38.303,15.954) AK1(0,16.212) AK2(-0.65,16.212) AK3(-1.3,16.174) AK4(-1.951,16.174) AK8(-4.303,16.451) AK18(-9.848,16.266) AK20(-10.801,16.266) AK21(-11.753,16.266) AK60(-36.678,16.523) AK61(-37.328,16.523) AK62(-37.978,16.629) AK63(-38.628,16.629) AL1(0,16.962) AL2(-0.65,16.962) AL3(-1.3,17) AL4(-1.951,17) AL5(-2.901,16.776) AL7(-3.739,16.776) AL8(-4.303,17.101) AL10(-5.658,16.776) AL11(-6.221,17.101) AL13(-7.576,16.776) AL15(-8.14,17.101) AL17(-9.222,16.583) AL18(-9.848,16.916) AL20(-10.801,16.916) AL21(-11.753,16.916) AL22(-12.706,16.916) AL23(-13.529,16.916) AL25(-14.504,16.916) AL26(-15.456,16.916) AL28(-16.409,16.916) AL29(-17.361,16.916) AL31(-18.26,16.591) AL32(-18.824,16.916) AL33(-19.726,16.916) AL35(-20.729,16.916) AL36(-21.58,16.916) AL38(-22.634,16.916) AL39(-23.542,16.591) AL40(-24.131,16.916) AL42(-24.944,16.916) AL43(-25.897,16.916) AL45(-26.874,16.916) AL46(-27.802,16.916) AL48(-28.856,16.916) AL49(-29.757,16.916) AL51(-30.761,16.916) AL52(-31.583,16.916) AL54(-32.61,16.916) AL55(-33.562,16.916) AL57(-34.509,16.916) AL58(-35.408,16.916) AL60(-36.352,17.169) AL61(-37.003,17.169) AM1(0,17.711) AM2(-0.65,17.711) AM3(-1.3,17.673) AM4(-1.951,17.673) AM5(-2.901,17.426) AM7(-3.739,17.426) AM8(-4.303,17.752) AM10(-5.658,17.426) AM11(-6.221,17.752) AM13(-7.576,17.426) AM15(-8.14,17.752) AM17(-9.222,17.233) AM18(-9.848,17.567) AM20(-10.801,17.567) AM21(-11.753,17.567) AM22(-12.706,17.567) AM23(-13.529,17.567) AM25(-14.504,17.567) AM26(-15.456,17.567) AM28(-16.409,17.567) AM29(-17.361,17.567) AM31(-18.26,17.242) AM32(-18.824,17.567) AM33(-19.726,17.567) AM35(-20.729,17.567) AM36(-21.58,17.567) AM38(-22.634,17.567) AM40(-24.131,17.567) AM42(-24.944,17.567) AM43(-25.897,17.567) AM45(-26.874,17.567) AM46(-27.802,17.567) AM48(-28.856,17.567) AM49(-29.757,17.567) AM51(-30.761,17.567) AM52(-31.583,17.567) AM54(-32.61,17.567) AM55(-33.562,17.567) AM57(-34.509,17.567) AM58(-35.408,17.567) AM60(-36.678,17.816) AM61(-37.328,17.816) AM62(-37.978,17.709) AM63(-38.628,17.709) AN1(0,18.46) AN2(-0.65,18.46) AN3(-1.3,18.498) AN4(-1.951,18.498) AN5(-2.901,18.077) AN7(-3.739,18.077) AN8(-4.303,18.402) AN10(-5.658,18.077) AN11(-6.221,18.402) AN13(-7.576,18.077) AN15(-8.14,18.402) AN17(-9.222,17.883) AN18(-9.848,18.217) AN20(-10.801,18.217) AN21(-11.753,18.217) AN22(-12.706,18.217) AN23(-13.529,18.217) AN25(-14.504,18.217) AN26(-15.456,18.217) AN28(-16.409,18.217) AN29(-17.361,18.217) AN31(-18.26,17.892) AN32(-18.824,18.217) AN33(-19.726,18.217) AN35(-20.729,18.217) AN36(-21.58,18.217) AN38(-22.634,18.217) AN39(-23.542,17.892) AN40(-24.131,18.217) AN42(-24.944,18.217) AN43(-25.897,18.217) AN45(-26.874,18.217) AN46(-27.802,18.217) AN48(-28.856,18.217) AN49(-29.757,18.217) AN51(-30.761,18.217) AN52(-31.583,18.217) AN54(-32.61,18.217) AN55(-33.562,18.217) AN57(-34.509,18.217) AN58(-35.408,18.217) AN60(-36.352,18.385) AN61(-37.003,18.385) AN62(-37.653,18.385) AN63(-38.303,18.385) AP1(0,19.21) AP2(-0.65,19.21) AP3(-1.3,19.171) AP4(-1.951,19.171) AP5(-2.901,18.727) AP7(-3.739,18.727) AP8(-4.303,19.052) AP10(-5.658,18.727) AP11(-6.221,19.052) AP13(-7.576,18.727) AP15(-8.14,19.052) AP17(-9.222,18.533) AP18(-9.848,18.867) AP20(-10.801,18.867) AP21(-11.753,18.867) AP22(-12.706,18.867) AP23(-13.529,18.867) AP25(-14.504,18.867) AP26(-15.456,18.867) AP28(-16.409,18.867) AP29(-17.361,18.867) AP31(-18.26,18.542) AP32(-18.824,18.867) AP33(-19.726,18.867) AP35(-20.729,18.867) AP36(-21.58,18.867) AP38(-22.634,18.867) AP39(-23.542,18.542) AP40(-24.131,18.867) AP42(-24.944,18.867) AP43(-25.897,18.867) AP45(-26.874,18.867) AP46(-27.802,18.867) AP48(-28.856,18.867) AP49(-29.757,18.867) AP51(-30.761,18.867) AP52(-31.583,18.867) AP54(-32.61,18.867) AP55(-33.562,18.867) AP57(-34.509,18.867) AP58(-35.408,18.867) AP60(-36.678,19.06) AP61(-37.328,19.06) AP62(-37.978,19.06) AP63(-38.628,19.06) AR5(-2.901,19.377) AR7(-3.739,19.377) AR8(-4.303,19.702) AR10(-5.658,19.377) AR11(-6.221,19.702) AR13(-7.576,19.377) AR15(-8.14,19.702) AR17(-9.222,19.184) AR18(-9.848,19.517) AR20(-10.801,19.517) AR21(-11.753,19.517) AR22(-12.706,19.517) AR23(-13.529,19.517) AR25(-14.504,19.517) AR26(-15.456,19.517) AR28(-16.409,19.517) AR29(-17.361,19.517) AR31(-18.26,19.192) AR32(-18.824,19.517) AR33(-19.726,19.517) AR35(-20.729,19.517) AR36(-21.58,19.517) AR38(-22.634,19.517) AR39(-23.542,19.192) AR40(-24.131,19.517) AR42(-24.944,19.517) AR43(-25.897,19.517) AR45(-26.874,19.517) AR46(-27.802,19.517) AR48(-28.856,19.517) AR49(-29.757,19.517) AR51(-30.761,19.517) AR52(-31.583,19.517) AR54(-32.61,19.517) AR55(-33.562,19.517) AR57(-34.509,19.517) AR58(-35.408,19.517) AT2(-0.65,19.959) AT3(-1.3,19.997) AT4(-1.951,19.997) AT5(-2.901,20.027) AT7(-3.739,20.027) AT10(-5.658,20.027) AT13(-7.576,20.027) AT35(-20.437,20.22) AT37(-22.011,20.22) AT40(-23.586,20.22) AT42(-25.161,20.22) AT43(-26.736,20.22) AT46(-28.311,20.22) AT49(-29.912,20.248) AT61(-37.003,19.634) AT62(-37.812,19.69) AU2(-0.655,20.647) AU3(-1.315,20.647) AU4(-1.976,20.647) AU6(-3.337,20.678) AU7(-4.163,20.678) AU8(-4.836,20.678) AU10(-5.661,20.678) AU11(-6.335,20.678) AU12(-7.16,20.678) AU14(-7.833,20.678) AU15(-8.659,20.678) AU16(-9.222,20.353) AU17(-9.86,20.678) AU18(-10.536,20.353) AU19(-11.105,20.678) AU20(-11.751,20.353) AU21(-12.397,20.678) AU22(-12.966,20.353) AU23(-13.642,20.678) AU24(-14.318,20.353) AU25(-14.993,20.678) AU26(-15.669,20.353) AU27(-16.238,20.678) AU28(-16.884,20.353) AU29(-17.531,20.678) AU30(-18.1,20.353) AU31(-18.775,20.678) AU33(-19.372,20.33) AU34(-19.974,20.678) AU35(-20.899,20.678) AU36(-21.549,20.678) AU37(-22.474,20.678) AU39(-23.124,20.678) AU40(-24.048,20.678) AU41(-24.699,20.678) AU42(-25.623,20.678) AU43(-26.274,20.678) AU44(-27.198,20.678) AU46(-27.848,20.678) AU47(-28.773,20.678) AU49(-29.423,20.678) AU50(-30.4,20.678) AU51(-30.98,20.353) AU52(-31.656,20.678) AU53(-32.331,20.353) AU54(-32.9,20.678) AU55(-33.547,20.353) AU56(-34.193,20.678) AU57(-34.762,20.353) AU58(-35.438,20.678) AU59(-36.002,20.353) AU60(-36.566,20.678) AU61(-37.277,20.401) AU62(-37.978,20.663) AV3(-1.321,21.308) AV4(-1.976,21.308) AV5(-2.664,21.328) AV6(-3.337,21.328) AV7(-4.163,21.328) AV8(-4.836,21.328) AV10(-5.661,21.328) AV11(-6.335,21.328) AV12(-7.16,21.328) AV14(-7.833,21.328) AV15(-8.659,21.328) AV16(-9.222,21.003) AV17(-9.86,21.328) AV18(-10.536,21.003) AV19(-11.105,21.328) AV20(-11.751,21.003) AV21(-12.397,21.328) AV22(-12.966,21.003) AV23(-13.642,21.328) AV24(-14.318,21.003) AV25(-14.993,21.328) AV26(-15.669,21.003) AV27(-16.238,21.328) AV28(-16.884,21.003) AV29(-17.531,21.328) AV30(-18.1,21.003) AV31(-18.775,21.328) AV33(-19.4,21.003) AV34(-20.024,21.328) AV35(-20.849,21.328) AV36(-21.599,21.328) AV37(-22.424,21.328) AV39(-23.173,21.328) AV40(-23.999,21.328) AV41(-24.748,21.328) AV42(-25.574,21.328) AV43(-26.323,21.328) AV44(-27.149,21.328) AV46(-27.898,21.328) AV47(-28.723,21.328) AV49(-29.473,21.328) AV50(-30.298,21.328) AV51(-30.98,21.003) AV52(-31.656,21.328) AV53(-32.331,21.003) AV54(-32.9,21.328) AV55(-33.547,21.003) AV56(-34.193,21.328) AV57(-34.762,21.003) AV58(-35.438,21.328) AV59(-36.002,21.003) AV60(-36.566,21.328) AV61(-37.302,21.051) AW4(-1.976,21.968) AW5(-2.626,21.978) AW6(-3.375,21.978) AW7(-4.125,21.978) AW8(-4.874,21.978) AW10(-5.623,21.978) AW11(-6.373,21.978) AW12(-7.122,21.978) AW14(-7.871,21.978) AW15(-8.621,21.978) AW16(-9.222,21.653) AW17(-9.86,21.978) AW18(-10.536,21.653) AW19(-11.211,21.978) AW21(-12.291,21.978) AW22(-12.966,21.653) AW23(-13.642,21.978) AW24(-14.318,21.653) AW25(-14.993,21.978) AW26(-15.669,21.653) AW27(-16.345,21.978) AW29(-17.424,21.978) AW30(-18.1,21.653) AW31(-18.775,21.978) AW33(-19.451,21.653) AW34(-20.024,21.978) AW35(-20.849,21.978) AW36(-21.599,21.978) AW37(-22.424,21.978) AW39(-23.173,21.978) AW40(-23.999,21.978) AW41(-24.748,21.978) AW42(-25.574,21.978) AW43(-26.323,21.978) AW44(-27.149,21.978) AW46(-27.898,21.978) AW47(-28.723,21.978) AW49(-29.473,21.978) AW50(-30.298,21.978) AW51(-30.98,21.653) AW52(-31.656,21.978) AW53(-32.331,21.653) AW54(-33.007,21.978) AW56(-34.087,21.978) AW57(-34.762,21.653) AW58(-35.438,21.978) AW59(-36.002,21.653) AW60(-36.566,21.978) AY6(-3.375,22.628) AY7(-4.125,22.628) AY8(-4.874,22.628) AY10(-5.623,22.628) AY11(-6.373,22.628) AY12(-7.122,22.628) AY14(-7.871,22.628) AY15(-8.621,22.628) AY16(-9.184,22.303) AY17(-9.86,22.628) AY18(-10.536,22.303) AY19(-11.211,22.628) AY21(-12.291,22.628) AY22(-12.966,22.303) AY23(-13.642,22.628) AY24(-14.318,22.303) AY25(-14.993,22.628) AY26(-15.669,22.303) AY27(-16.345,22.628) AY29(-17.424,22.628) AY30(-18.1,22.303) AY31(-18.775,22.628) AY33(-19.451,22.303) AY34(-20.024,22.628) AY35(-20.849,22.628) AY36(-21.599,22.628) AY37(-22.424,22.628) AY39(-23.173,22.628) AY40(-23.999,22.628) AY41(-24.748,22.628) AY42(-25.574,22.628) AY43(-26.323,22.628) AY44(-27.149,22.628) AY46(-27.898,22.628) AY47(-28.723,22.628) AY49(-29.473,22.628) AY50(-30.298,22.628) AY51(-30.98,22.303) AY52(-31.656,22.628) AY53(-32.331,22.303) AY54(-33.007,22.628) AY56(-34.087,22.628) AY57(-34.762,22.303) AY58(-35.438,22.628) B4(-1.922,0.65) B5(-3.138,0.643) B6(-4.119,0.643) B8(-4.891,0.643) B9(-5.716,0.643) B11(-6.697,0.643) B12(-7.469,0.643) B14(-8.294,0.643) B15(-9.275,0.643) B17(-10.047,0.643) B18(-10.872,0.643) B20(-11.853,0.643) B21(-12.272,1.196) B22(-12.625,0.643) B23(-13.451,0.643) B24(-14.023,0.975) B25(-14.714,0.65) B26(-15.277,0.975) B27(-15.84,0.65) B28(-16.531,0.975) B29(-17.221,0.65) B30(-17.785,0.975) B31(-18.348,0.65) B32(-19.038,0.975) B33(-19.729,0.65) B34(-20.292,0.975) B35(-20.855,0.65) B36(-21.546,0.975) B37(-22.236,0.65) B38(-22.8,0.975) B39(-23.363,0.65) B40(-24.053,0.975) B41(-24.744,0.65) B42(-25.307,0.975) B43(-25.87,0.65) B44(-26.561,0.975) B45(-27.251,0.65) B46(-27.815,0.975) B47(-28.378,0.65) B48(-29.068,0.975) B49(-29.759,0.65) B50(-30.322,0.975) B51(-30.885,0.65) B52(-31.576,0.975) B53(-32.266,0.65) B54(-32.83,0.975) B55(-33.393,0.65) B56(-34.083,0.975) B57(-34.774,0.65) B58(-35.337,0.975) B59(-35.9,0.65) B60(-36.665,0.66) C3(-1.302,1.302) C4(-2.118,1.272) C5(-2.772,1.196) C6(-3.776,1.196) C8(-4.538,1.196) C9(-5.351,1.196) C11(-6.354,1.196) C12(-7.116,1.196) C14(-7.929,1.196) C15(-8.932,1.196) C17(-9.694,1.196) C18(-10.507,1.196) C20(-11.51,1.196) C21(-11.891,1.786) C22(-12.678,1.786) C23(-13.085,1.196) C24(-14.051,2.032) C25(-14.714,1.3) C26(-15.277,1.626) C27(-15.84,1.3) C28(-16.558,2.032) C29(-17.221,1.3) C30(-17.785,1.626) C31(-18.348,1.3) C32(-19.066,2.032) C33(-19.729,1.3) C34(-20.292,1.626) C35(-20.855,1.3) C36(-21.573,2.032) C37(-22.236,1.3) C38(-22.8,1.626) C39(-23.363,1.3) C40(-24.081,2.032) C41(-24.744,1.3) C42(-25.307,1.626) C43(-25.87,1.3) C44(-26.588,2.032) C45(-27.251,1.3) C46(-27.815,1.626) C47(-28.378,1.3) C48(-29.07,2.032) C49(-29.759,1.3) C50(-30.322,1.626) C51(-30.885,1.3) C52(-31.578,1.991) C53(-32.266,1.3) C54(-32.83,1.626) C55(-33.393,1.3) C56(-34.085,1.991) C57(-34.774,1.3) C58(-35.337,1.626) C59(-35.9,1.3) C61(-37.003,1.237) D2(-0.65,2.075) D3(-1.3,2.037) D5(-2.678,1.842) D6(-3.369,1.786) D8(-4.157,1.786) D9(-4.944,1.786) D11(-5.852,1.786) D12(-6.735,1.786) D14(-7.522,1.786) D15(-8.43,1.786) D17(-9.313,1.786) D18(-10.1,1.786) D20(-11.008,1.786) D21(-12.235,2.423) D23(-13.377,1.786) D25(-14.714,1.951) D26(-15.277,2.276) D27(-15.84,1.951) D29(-17.221,1.951) D30(-17.785,2.276) D31(-18.348,1.951) D33(-19.729,1.951) D34(-20.292,2.276) D35(-20.855,1.951) D37(-22.236,1.951) D38(-22.8,2.276) D39(-23.363,1.951) D41(-24.744,1.951) D42(-25.307,2.276) D43(-25.87,1.951) D45(-27.251,1.951) D46(-27.815,2.276) D47(-28.378,1.951) D49(-29.759,1.951) D50(-30.322,2.276) D51(-30.885,1.951) D53(-32.266,1.951) D54(-32.83,2.276) D55(-33.393,1.951) D57(-34.774,1.951) D58(-35.337,2.276) D59(-35.9,1.951) D60(-36.678,1.801) D61(-37.328,1.801) D62(-37.978,2.035) E2(-0.65,2.725) E3(-1.3,2.687) E4(-1.951,2.687) E5(-2.602,2.619) E6(-3.554,2.619) E8(-4.507,2.619) E10(-5.459,2.619) E11(-6.412,2.619) E13(-7.364,2.619) E15(-8.317,2.619) E17(-9.269,2.619) E18(-10.222,2.619) E20(-11.174,2.619) E59(-36.027,2.647) E60(-36.678,2.647) E61(-37.328,2.647) E62(-37.978,2.685) F2(-0.65,3.474) F3(-1.3,3.512) F4(-1.951,3.512) F5(-2.602,3.269) F6(-3.554,3.269) F8(-4.507,3.269) F10(-5.459,3.269) F11(-6.412,3.269) F13(-7.364,3.269) F15(-8.317,3.269) F17(-9.269,3.269) F18(-10.222,3.269) F20(-11.174,3.269) F59(-36.027,3.472) F60(-36.678,3.472) F61(-37.328,3.472) F62(-37.978,3.434) F63(-38.628,3.434) G1(0,4.224) G2(-0.65,4.224) G3(-1.3,4.185) G4(-1.951,4.185) G5(-2.602,3.919) G6(-3.554,3.919) G8(-4.507,3.919) G10(-5.459,3.919) G11(-6.412,3.919) G13(-7.364,3.919) G15(-8.317,3.919) G17(-9.269,3.919) G18(-10.222,3.919) G20(-11.174,3.919) H5(-2.602,4.569) H6(-3.554,4.569) H8(-4.507,4.569) H10(-5.459,4.569) H11(-6.412,4.569) H13(-7.364,4.569) H15(-8.317,4.569) H17(-9.269,4.569) H18(-10.222,4.569) H20(-11.174,4.569) H59(-36.027,4.145) H60(-36.678,4.145) H61(-37.328,4.145) H62(-37.978,4.183) H63(-38.628,4.183) J1(0,4.973) J2(-0.65,4.973) J3(-1.3,5.011) J4(-1.951,5.011) J5(-2.627,5.22) J6(-3.567,5.22) J8(-4.507,5.22) J10(-5.459,5.22) J11(-6.412,5.22) J13(-7.364,5.22) J15(-8.317,5.22) J17(-9.269,5.22) J18(-10.222,5.22) J20(-11.174,5.22) J21(-12.095,4.986) J59(-36.027,4.971) J60(-36.678,4.971) J61(-37.328,4.971) J62(-37.978,4.933) J63(-38.628,4.933) K1(0,5.722) K2(-0.65,5.722) K3(-1.3,5.684) K4(-1.951,5.684) K59(-36.027,5.644) K60(-36.678,5.644) K61(-37.328,5.644) K62(-37.978,5.682) K63(-38.628,5.682) L1(0,6.471) L2(-0.65,6.471) L3(-1.3,6.51) L4(-1.951,6.51) L5(-2.637,6.338) L6(-3.287,6.338) L7(-3.937,6.338) L8(-4.587,6.338) L59(-36.027,6.469) L60(-36.678,6.469) L61(-37.328,6.469) L62(-37.978,6.431) L63(-38.628,6.431) N1(0,7.221) N2(-0.65,7.221) N3(-1.3,7.183) N4(-1.951,7.183) N5(-2.637,7.29) N6(-3.287,7.29) N7(-3.937,7.29) N8(-4.587,7.29) N59(-36.027,7.142) N60(-36.678,7.142) N61(-37.328,7.142) N62(-37.978,7.181) N63(-38.628,7.181) P1(0,7.97) P2(-0.65,7.97) P3(-1.3,8.008) P4(-1.951,8.008) P59(-36.027,7.968) P60(-36.678,7.968) P61(-37.328,7.968) P62(-37.978,7.93) P63(-38.628,7.93) R5(-2.637,8.243) R6(-3.287,8.243) R7(-3.937,8.243) R8(-4.587,8.243) T1(0,8.719) T2(-0.65,8.719) T3(-1.3,8.681) T4(-1.951,8.681) T59(-36.027,8.641) T60(-36.678,8.641) T61(-37.328,8.641) T62(-37.978,8.679) T63(-38.628,8.679) U1(0,9.469) U2(-0.65,9.469) U3(-1.3,9.507) U4(-1.951,9.507) U5(-2.637,9.195) U6(-3.287,9.195) U7(-3.937,9.195) U8(-4.587,9.195) U59(-36.027,9.467) U60(-36.678,9.467) U61(-37.328,9.467) U62(-37.978,9.428) U63(-38.628,9.428) V1(0,10.218) V2(-0.65,10.218) V3(-1.3,10.18) V4(-1.951,10.18) V5(-2.637,10.148) V6(-3.287,10.148) V7(-3.937,10.148) V8(-4.587,10.148) V59(-36.027,10.14) V60(-36.678,10.14) V61(-37.328,10.14) V62(-37.978,10.178) V63(-38.628,10.178) Y1(0,10.967) Y2(-0.65,10.967) Y3(-1.3,11.005) Y4(-1.951,11.005) Y5(-2.637,11.1) Y6(-3.287,11.1) Y7(-3.937,11.1) Y8(-4.587,11.1) Y59(-36.027,10.965) Y60(-36.678,10.965) Y61(-37.328,10.965) Y62(-37.978,10.927) Y63(-38.628,10.927)
  round 0.33 smd: AK22(-12.655,16.266) AK23(-13.529,16.266) AK25(-14.504,16.266) AK26(-15.456,16.266) AK28(-16.409,16.266) AK29(-17.311,16.266) AK32(-18.824,16.266) AK33(-19.726,16.266) AK35(-20.729,16.266) AK36(-21.58,16.266) AK38(-22.609,16.266) AK40(-24.106,16.266) AK42(-24.944,16.266) AK43(-25.897,16.266) AK45(-26.874,16.266) AK46(-27.776,16.266) AK48(-28.83,16.266) AK49(-29.732,16.266) AK51(-30.735,16.266) AK52(-31.583,16.266) AK54(-32.61,16.266) AK55(-33.562,16.266) AK57(-34.509,16.266) AK58(-35.408,16.266)
HB_A090420-SAHR21_4P
  oval 0.61x1.499 smd: 1(0,0) 2(1,0) 3(2,0) 4(3,0)
  rect 2.489x2.21 smd: 5(-3,-3.15) 6(6,-3.15)
HB_A823020-SBHR21_30P
  oval 0.305x1.295 smd: 1(0,0) 2(0.8,0) 3(1.6,0) 4(2.4,0) 5(3.2,0) 6(4,0) 7(4.8,0) 8(5.6,0) 9(6.4,0) 10(7.2,0) 11(8,0) 12(8.8,0) 13(9.6,0) 14(10.4,0) 15(11.2,0) 16(12,0) 17(12.8,0) 18(13.6,0) 19(14.4,0) 20(15.2,0) 21(16,0) 22(16.8,0) 23(17.6,0) 24(18.4,0) 25(19.2,0) 26(20,0) 27(20.8,0) 28(21.6,0) 29(22.4,0) 30(23.2,0)
  rect 1.803x2.21 smd: 31(25.55,-5.65) 32(-2.35,-5.65)
IP4223CZ6_SO6
  oval 0.508x1.422 smd: 1(0,0) 2(0.95,0) 3(1.9,0) 4(1.9,2.35) 5(0.95,2.35) 6(0,2.35)
IP4292CZ10-TBR_XSON10_2P5X1
  oval 0.254x0.889 smd: 1(0,0)
  oval 0.254x0.838 smd: 2(0.5,-0.025) 3(1,-0.025) 4(1.5,-0.025) 5(2,-0.025) 6(2,1.125) 7(1.5,1.125) 8(1,1.125) 9(0.5,1.125) 10(0,1.125)
ISL62881HRZ-T_QFN28_4X4
  oval 0.203x1.092 smd: 1(0,0) 2(0.4,0) 3(0.8,0) 4(1.2,0) 5(1.6,0) 6(2,0) 7(2.4,0) 15(2.4,3.9) 16(2,3.9) 17(1.6,3.9) 18(1.2,3.9) 19(0.8,3.9) 20(0.4,3.9) 21(0,3.9)
  oval 1.092x0.203 smd: 8(3.15,0.75) 9(3.15,1.15) 10(3.15,1.55) 11(3.15,1.95) 12(3.15,2.35) 13(3.15,2.75) 14(3.15,3.15) 22(-0.75,3.15) 23(-0.75,2.75) 24(-0.75,2.35) 25(-0.75,1.95) 26(-0.75,1.55) 27(-0.75,1.15) 28(-0.75,0.75)
  rect 2.388x2.388 smd: 29(1.2,1.95)
JESS_UCNR2210M008-0_8P
  oval 0.508x1.295 smd: 1(0,0) 2(-1,0) 3(-2,0) 4(-3,0) 5(-4,0) 6(-5,0) 7(-6,0) 8(-7,0)
  rect 2.489x1.905 smd: 9(-9.65,3.3) 10(2.65,3.3)
JUMP_43X39
  custom 0.191x0.191 smd: 1(0,0) 2(0.914,0)
JUMP_43X79
  custom 0.188x0.188 smd: 1(0,0) 2(1.1,0)
JUMP_43X118
  custom 0.187x0.187 smd: 1(0,0) 2(1.1,0)
K4B4G1646B-HYH9_FBGA_96P
  round 0.343 smd: A1(0,0) A2(0.8,0) A3(1.6,0) A7(4.8,0) A8(5.6,0) A9(6.4,0) B1(0,-0.8) B2(0.8,-0.8) B3(1.6,-0.8) B7(4.8,-0.8) B8(5.6,-0.8) B9(6.4,-0.8) C1(0,-1.6) C2(0.8,-1.6) C3(1.6,-1.6) C7(4.8,-1.6) C8(5.6,-1.6) C9(6.4,-1.6) D1(0,-2.4) D2(0.8,-2.4) D3(1.6,-2.4) D7(4.8,-2.4) D8(5.6,-2.4) D9(6.4,-2.4) E1(0,-3.2) E2(0.8,-3.2) E3(1.6,-3.2) E7(4.8,-3.2) E8(5.6,-3.2) E9(6.4,-3.2) F1(0,-4) F2(0.8,-4) F3(1.6,-4) F7(4.8,-4) F8(5.6,-4) F9(6.4,-4) G1(0,-4.8) G2(0.8,-4.8) G3(1.6,-4.8) G7(4.8,-4.8) G8(5.6,-4.8) G9(6.4,-4.8) H1(0,-5.6) H2(0.8,-5.6) H3(1.6,-5.6) H7(4.8,-5.6) H8(5.6,-5.6) H9(6.4,-5.6) J1(0,-6.4) J2(0.8,-6.4) J3(1.6,-6.4) J7(4.8,-6.4) J8(5.6,-6.4) J9(6.4,-6.4) K1(0,-7.2) K2(0.8,-7.2) K3(1.6,-7.2) K7(4.8,-7.2) K8(5.6,-7.2) K9(6.4,-7.2) L1(0,-8) L2(0.8,-8) L3(1.6,-8) L7(4.8,-8) L8(5.6,-8) L9(6.4,-8) M1(0,-8.8) M2(0.8,-8.8) M3(1.6,-8.8) M7(4.8,-8.8) M8(5.6,-8.8) M9(6.4,-8.8) N1(0,-9.6) N2(0.8,-9.6) N3(1.6,-9.6) N7(4.8,-9.6) N8(5.6,-9.6) N9(6.4,-9.6) P1(0,-10.4) P2(0.8,-10.4) P3(1.6,-10.4) P7(4.8,-10.4) P8(5.6,-10.4) P9(6.4,-10.4) R1(0,-11.2) R2(0.8,-11.2) R3(1.6,-11.2) R7(4.8,-11.2) R8(5.6,-11.2) R9(6.4,-11.2) T1(0,-12) T2(0.8,-12) T3(1.6,-12) T7(4.8,-12) T8(5.6,-12) T9(6.4,-12)
KB9012QF-A2_LQFP128_14X14
  oval 0.203x1.753 smd: 1(0,0) 2(0.4,0) 3(0.8,0) 4(1.2,0) 5(1.6,0) 6(2,0) 7(2.4,0) 8(2.8,0) 9(3.2,0) 10(3.6,0) 11(4,0) 12(4.4,0) 13(4.8,0) 14(5.2,0) 15(5.6,0) 16(6,0) 17(6.4,0) 18(6.8,0) 19(7.2,0) 20(7.6,0) 21(8,0) 22(8.4,0) 23(8.8,0) 24(9.2,0) 25(9.6,0) 26(10,0) 27(10.4,0) 28(10.8,0) 29(11.2,0) 30(11.6,0) 31(12,0) 32(12.4,0) 65(12.4,15.654) 66(12,15.654) 67(11.6,15.654) 68(11.2,15.654) 69(10.8,15.654) 70(10.4,15.654) 71(10,15.654) 72(9.6,15.654) 73(9.2,15.654) 74(8.8,15.654) 75(8.4,15.654) 76(8,15.654) 77(7.6,15.654) 78(7.2,15.654) 79(6.8,15.654) 80(6.4,15.654) 81(6,15.654) 82(5.6,15.654) 83(5.2,15.654) 84(4.8,15.654) 85(4.4,15.654) 86(4,15.654) 87(3.6,15.654) 88(3.2,15.654) 89(2.8,15.654) 90(2.4,15.654) 91(2,15.654) 92(1.6,15.654) 93(1.2,15.654) 94(0.8,15.654) 95(0.4,15.654) 96(0,15.654)
  oval 1.753x0.203 smd: 33(14.027,1.627) 34(14.027,2.027) 35(14.027,2.427) 36(14.027,2.827) 37(14.027,3.227) 38(14.027,3.627) 39(14.027,4.027) 40(14.027,4.427) 41(14.027,4.827) 42(14.027,5.227) 43(14.027,5.627) 44(14.027,6.027) 45(14.027,6.427) 46(14.027,6.827) 47(14.027,7.227) 48(14.027,7.627) 49(14.027,8.027) 50(14.027,8.427) 51(14.027,8.827) 52(14.027,9.227) 53(14.027,9.627) 54(14.027,10.027) 55(14.027,10.427) 56(14.027,10.827) 57(14.027,11.227) 58(14.027,11.627) 59(14.027,12.027) 60(14.027,12.427) 61(14.027,12.827) 62(14.027,13.227) 63(14.027,13.627) 64(14.027,14.027) 97(-1.627,14.027) 98(-1.627,13.627) 99(-1.627,13.227) 100(-1.627,12.827) 101(-1.627,12.427) 102(-1.627,12.027) 103(-1.627,11.627) 104(-1.627,11.227) 105(-1.627,10.827) 106(-1.627,10.427) 107(-1.627,10.027) 108(-1.627,9.627) 109(-1.627,9.227) 110(-1.627,8.827) 111(-1.627,8.427) 112(-1.627,8.027) 113(-1.627,7.627) 114(-1.627,7.227) 115(-1.627,6.827) 116(-1.627,6.427) 117(-1.627,6.027) 118(-1.627,5.627) 119(-1.627,5.227) 120(-1.627,4.827) 121(-1.627,4.427) 122(-1.627,4.027) 123(-1.627,3.627) 124(-1.627,3.227) 125(-1.627,2.827) 126(-1.627,2.427) 127(-1.627,2.027) 128(-1.627,1.627)
KC_FBMA-L10-160808-800LMT_2P
  rect 0.889x1.092 smd: 1(0,0) 2(1.5,0)
KC_FBMA-L11-160808-800LMT_2P
  rect 0.889x1.092 smd: 1(0,0) 2(1.5,0)
KC_FBMA-L11-201209-221LMA30_2P
  rect 0.838x1.397 smd: 1(0,0) 2(1.65,0)
KC_WCM-2012HS-900T_4P
  rect 0.889x0.406 smd: 1(0,0) 2(1.7,0) 3(1.7,-0.8) 4(0,-0.8)
L03ESDL5V0CG3-2_SOT-523-3
  oval 0.406x0.787 smd: 1(0,0) 2(-0.5,-1.4) 3(0.5,-1.4)
L30ESDL5V0C3-2_SOT23-3
  oval 1.016x1.524 smd: 1(0,0) 2(0.965,2.083) 3(-0.965,2.083)
L_1812-1806
  oval 1.016x3.708 smd: 1(0,0) 2(4.013,0)
LCN_DAN06-K4406-0102_204P
  round 1.6 hole 1.6 unplated: (-1.75,4.1)
  round 1.092 hole 1.092 unplated: (65.05,4.1)
  oval 0.356x2.007 smd: 1(0,0) 2(0.3,8.2) 3(0.6,0) 4(0.9,8.2) 5(1.2,0) 6(1.5,8.2) 7(1.8,0) 8(2.1,8.2) 9(2.4,0) 10(2.7,8.2) 11(3,0) 12(3.3,8.2) 13(3.6,0) 14(3.9,8.2) 15(4.2,0) 16(4.5,8.2) 17(4.8,0) 18(5.1,8.2) 19(5.4,0) 20(5.7,8.2) 21(6,0) 22(6.3,8.2) 23(6.6,0) 24(6.9,8.2) 25(7.2,0) 26(7.5,8.2) 27(7.8,0) 28(8.1,8.2) 29(8.4,0) 30(8.7,8.2) 31(9,0) 32(9.3,8.2) 33(9.6,0) 34(9.9,8.2) 35(10.2,0) 36(10.5,8.2) 37(10.8,0) 38(11.1,8.2) 39(11.4,0) 40(11.7,8.2) 41(12,0) 42(12.3,8.2) 43(12.6,0) 44(12.9,8.2) 45(13.2,0) 46(13.5,8.2) 47(13.8,0) 48(14.1,8.2) 49(14.4,0) 50(14.7,8.2) 51(15,0) 52(15.3,8.2) 53(15.6,0) 54(15.9,8.2) 55(16.2,0) 56(16.5,8.2) 57(16.8,0) 58(17.1,8.2) 59(17.4,0) 60(17.7,8.2) 61(18,0) 62(18.3,8.2) 63(18.6,0) 64(18.9,8.2) 65(19.2,0) 66(19.5,8.2) 67(19.8,0) 68(20.1,8.2) 69(20.4,0) 70(20.7,8.2) 71(21,0) 72(21.3,8.2) 73(24,0) 74(24.3,8.2) 75(24.6,0) 76(24.9,8.2) 77(25.2,0) 78(25.5,8.2) 79(25.8,0) 80(26.1,8.2) 81(26.4,0) 82(26.7,8.2) 83(27,0) 84(27.3,8.2) 85(27.6,0) 86(27.9,8.2) 87(28.2,0) 88(28.5,8.2) 89(28.8,0) 90(29.1,8.2) 91(29.4,0) 92(29.7,8.2) 93(30,0) 94(30.3,8.2) 95(30.6,0) 96(30.9,8.2) 97(31.2,0) 98(31.5,8.2) 99(31.8,0) 100(32.1,8.2) 101(32.4,0) 102(32.7,8.2) 103(33,0) 104(33.3,8.2) 105(33.6,0) 106(33.9,8.2) 107(34.2,0) 108(34.5,8.2) 109(34.8,0) 110(35.1,8.2) 111(35.4,0) 112(35.7,8.2) 113(36,0) 114(36.3,8.2) 115(36.6,0) 116(36.9,8.2) 117(37.2,0) 118(37.5,8.2) 119(37.8,0) 120(38.1,8.2) 121(38.4,0) 122(38.7,8.2) 123(39,0) 124(39.3,8.2) 125(39.6,0) 126(39.9,8.2) 127(40.2,0) 128(40.5,8.2) 129(40.8,0) 130(41.1,8.2) 131(41.4,0) 132(41.7,8.2) 133(42,0) 134(42.3,8.2) 135(42.6,0) 136(42.9,8.2) 137(43.2,0) 138(43.5,8.2) 139(43.8,0) 140(44.1,8.2) 141(44.4,0) 142(44.7,8.2) 143(45,0) 144(45.3,8.2) 145(45.6,0) 146(45.9,8.2) 147(46.2,0) 148(46.5,8.2) 149(46.8,0) 150(47.1,8.2) 151(47.4,0) 152(47.7,8.2) 153(48,0) 154(48.3,8.2) 155(48.6,0) 156(48.9,8.2) 157(49.2,0) 158(49.5,8.2) 159(49.8,0) 160(50.1,8.2) 161(50.4,0) 162(50.7,8.2) 163(51,0) 164(51.3,8.2) 165(51.6,0) 166(51.9,8.2) 167(52.2,0) 168(52.5,8.2) 169(52.8,0) 170(53.1,8.2) 171(53.4,0) 172(53.7,8.2) 173(54,0) 174(54.3,8.2) 175(54.6,0) 176(54.9,8.2) 177(55.2,0) 178(55.5,8.2) 179(55.8,0) 180(56.1,8.2) 181(56.4,0) 182(56.7,8.2) 183(57,0) 184(57.3,8.2) 185(57.6,0) 186(57.9,8.2) 187(58.2,0) 188(58.5,8.2) 189(58.8,0) 190(59.1,8.2) 191(59.4,0) 192(59.7,8.2) 193(60,0) 194(60.3,8.2) 195(60.6,0) 196(60.9,8.2) 197(61.2,0) 198(61.5,8.2) 199(61.8,0) 200(62.1,8.2) 201(62.4,0) 202(62.7,8.2) 203(63,0) 204(63.3,8.2)
  rect 3.505x4.597 smd: 205(-1.15,16.1) 206(64.45,16.1)
